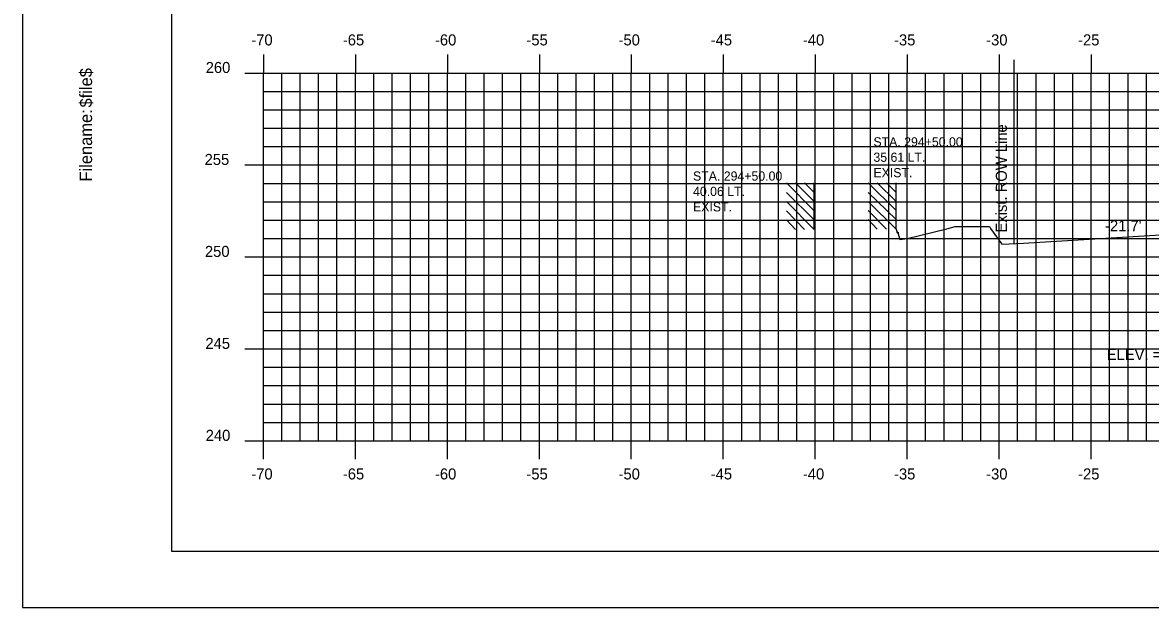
# Model space of a CAD drawing. Extents: x 859352 to 859522, y 366268 to 366378.
# Drawn here: x 859352 to 859413.3, y 366268.2 to 366300 of the extents above; entities that cross this region are included whole.
import ezdxf

# ---------------------------------------------------------------- set-up
doc = ezdxf.new("R2010")
doc.units = 0
for name, color, linetype in [('BORDER', 7, 'Continuous'), ('D_Text_Monospaced', 7, 'Continuous'), ('D_Text_Standard', 7, 'Continuous'), ('E_ROW_Line', 7, 'Continuous'), ('H_V ANNOTATION', 7, 'Continuous'), ('MAJOR', 7, 'Continuous'), ('MINOR', 7, 'Continuous'), ('PLOT BOUNDARY', 7, 'Continuous'), ('S_Buildings', 7, 'Continuous'), ('S_Roadway_Centerline', 7, 'Continuous')]:
    doc.layers.add(name, color=color, linetype=linetype)

msp = doc.modelspace()

# ---------------------------------------------------------------- linework, layer by layer
at = {"layer": 'BORDER'}
for p, q in [((859360.13, 366376.236), (859360.13, 366271.236)), ((859360.13, 366271.236), (859520.13, 366271.236))]:
    msp.add_line(p, q, dxfattribs=at)
at = {"layer": 'E_ROW_Line'}
msp.add_line((859405.943, 366287.961), (859405.943, 366297.961), dxfattribs=at)
at = {"layer": 'MAJOR'}
for p, q in [((859365.129, 366298.238), (859365.129, 366297.236)), ((859370.129, 366298.238), (859370.129, 366297.236)), ((859375.129, 366298.238), (859375.129, 366297.236)), ((859380.129, 366298.238), (859380.129, 366297.236)), ((859385.129, 366298.238), (859385.129, 366297.236)), ((859390.129, 366298.238), (859390.129, 366297.236)), ((859395.129, 366298.238), (859395.129, 366297.236)), ((859400.129, 366298.238), (859400.129, 366297.236)), ((859405.129, 366298.238), (859405.129, 366297.236)), ((859410.129, 366298.238), (859410.129, 366297.236)), ((859364.127, 366297.236), (859365.129, 366297.236)), ((859365.129, 366297.236), (859505.129, 366297.236)), ((859365.129, 366277.236), (859365.129, 366297.236)), ((859365.129, 366277.236), (859365.129, 366297.236)), ((859365.129, 366297.236), (859505.129, 366297.236)), ((859370.129, 366277.236), (859370.129, 366297.236)), ((859375.129, 366277.236), (859375.129, 366297.236)), ((859380.129, 366277.236), (859380.129, 366297.236)), ((859385.129, 366277.236), (859385.129, 366297.236)), ((859390.129, 366277.236), (859390.129, 366297.236)), ((859395.129, 366277.236), (859395.129, 366297.236)), ((859400.129, 366277.236), (859400.129, 366297.236)), ((859405.129, 366277.236), (859405.129, 366297.236)), ((859410.129, 366277.236), (859410.129, 366297.236)), ((859364.127, 366292.236), (859365.129, 366292.236)), ((859365.129, 366292.236), (859505.129, 366292.236)), ((859364.127, 366287.236), (859365.129, 366287.236)), ((859365.129, 366287.236), (859505.129, 366287.236)), ((859364.127, 366282.236), (859365.129, 366282.236)), ((859365.129, 366282.236), (859505.129, 366282.236)), ((859364.127, 366277.236), (859365.129, 366277.236)), ((859365.129, 366277.236), (859505.129, 366277.236)), ((859365.129, 366277.236), (859505.129, 366277.236)), ((859365.129, 366276.234), (859365.129, 366277.236)), ((859370.129, 366276.234), (859370.129, 366277.236)), ((859375.129, 366276.234), (859375.129, 366277.236)), ((859380.129, 366276.234), (859380.129, 366277.236)), ((859385.129, 366276.234), (859385.129, 366277.236)), ((859390.129, 366276.234), (859390.129, 366277.236)), ((859395.129, 366276.234), (859395.129, 366277.236)), ((859400.129, 366276.234), (859400.129, 366277.236)), ((859405.129, 366276.234), (859405.129, 366277.236)), ((859410.129, 366276.234), (859410.129, 366277.236))]:
    msp.add_line(p, q, dxfattribs=at)
at = {"layer": 'MINOR'}
for p, q in [((859366.129, 366277.236), (859366.129, 366297.236)), ((859367.129, 366277.236), (859367.129, 366297.236)), ((859368.129, 366277.236), (859368.129, 366297.236)), ((859369.129, 366277.236), (859369.129, 366297.236)), ((859371.129, 366277.236), (859371.129, 366297.236)), ((859372.129, 366277.236), (859372.129, 366297.236)), ((859373.129, 366277.236), (859373.129, 366297.236)), ((859374.129, 366277.236), (859374.129, 366297.236)), ((859376.129, 366277.236), (859376.129, 366297.236)), ((859377.129, 366277.236), (859377.129, 366297.236)), ((859378.129, 366277.236), (859378.129, 366297.236)), ((859379.129, 366277.236), (859379.129, 366297.236)), ((859381.129, 366277.236), (859381.129, 366297.236)), ((859382.129, 366277.236), (859382.129, 366297.236)), ((859383.129, 366277.236), (859383.129, 366297.236)), ((859384.129, 366277.236), (859384.129, 366297.236)), ((859386.129, 366277.236), (859386.129, 366297.236)), ((859387.129, 366277.236), (859387.129, 366297.236)), ((859388.129, 366277.236), (859388.129, 366297.236)), ((859389.129, 366277.236), (859389.129, 366297.236)), ((859391.129, 366277.236), (859391.129, 366297.236)), ((859392.129, 366277.236), (859392.129, 366297.236)), ((859393.129, 366277.236), (859393.129, 366297.236)), ((859394.129, 366277.236), (859394.129, 366297.236)), ((859396.129, 366277.236), (859396.129, 366297.236)), ((859397.129, 366277.236), (859397.129, 366297.236)), ((859398.129, 366277.236), (859398.129, 366297.236)), ((859399.129, 366277.236), (859399.129, 366297.236)), ((859401.129, 366277.236), (859401.129, 366297.236)), ((859402.129, 366277.236), (859402.129, 366297.236)), ((859403.129, 366277.236), (859403.129, 366297.236)), ((859404.129, 366277.236), (859404.129, 366297.236)), ((859406.129, 366277.236), (859406.129, 366297.236)), ((859407.129, 366277.236), (859407.129, 366297.236)), ((859408.129, 366277.236), (859408.129, 366297.236)), ((859409.129, 366277.236), (859409.129, 366297.236)), ((859411.129, 366277.236), (859411.129, 366297.236)), ((859412.129, 366277.236), (859412.129, 366297.236)), ((859413.129, 366277.236), (859413.129, 366297.236)), ((859365.129, 366296.236), (859505.129, 366296.236)), ((859365.129, 366296.236), (859366.131, 366296.236)), ((859365.129, 366295.236), (859505.129, 366295.236)), ((859365.129, 366295.236), (859366.131, 366295.236)), ((859365.129, 366294.236), (859505.129, 366294.236)), ((859365.129, 366294.236), (859366.131, 366294.236)), ((859365.129, 366293.236), (859505.129, 366293.236)), ((859365.129, 366293.236), (859366.131, 366293.236)), ((859365.129, 366291.236), (859505.129, 366291.236)), ((859365.129, 366291.236), (859366.131, 366291.236)), ((859365.129, 366290.236), (859505.129, 366290.236)), ((859365.129, 366290.236), (859366.131, 366290.236)), ((859365.129, 366289.236), (859505.129, 366289.236)), ((859365.129, 366289.236), (859366.131, 366289.236)), ((859365.129, 366288.236), (859505.129, 366288.236)), ((859365.129, 366288.236), (859366.131, 366288.236)), ((859365.129, 366286.236), (859505.129, 366286.236)), ((859365.129, 366286.236), (859366.131, 366286.236)), ((859365.129, 366285.236), (859505.129, 366285.236)), ((859365.129, 366285.236), (859366.131, 366285.236)), ((859365.129, 366284.236), (859505.129, 366284.236)), ((859365.129, 366284.236), (859366.131, 366284.236)), ((859365.129, 366283.236), (859505.129, 366283.236)), ((859365.129, 366283.236), (859366.131, 366283.236)), ((859365.129, 366281.236), (859505.129, 366281.236)), ((859365.129, 366281.236), (859366.131, 366281.236)), ((859365.129, 366280.236), (859505.129, 366280.236)), ((859365.129, 366280.236), (859366.131, 366280.236)), ((859365.129, 366279.236), (859505.129, 366279.236)), ((859365.129, 366279.236), (859366.131, 366279.236)), ((859365.129, 366278.236), (859505.129, 366278.236)), ((859365.129, 366278.236), (859366.131, 366278.236))]:
    msp.add_line(p, q, dxfattribs=at)
at = {"layer": 'PLOT BOUNDARY'}
msp.add_lwpolyline([(859352.036, 366268.177), (859522.036, 366268.177), (859522.036, 366378.177), (859352.036, 366378.177)], close=True, dxfattribs=at)
at = {"layer": 'S_Buildings'}
for p, q in [((859395.067, 366289.75), (859393.558, 366291.259)), ((859395.067, 366290.242), (859394.05, 366291.259)), ((859395.067, 366290.735), (859394.542, 366291.259)), ((859395.067, 366288.733), (859395.067, 366291.259)), ((859399.518, 366289.761), (859398.008, 366291.27)), ((859399.518, 366290.253), (859398.501, 366291.27)), ((859399.518, 366290.745), (859398.993, 366291.27)), ((859399.518, 366288.744), (859399.518, 366291.27)), ((859395.067, 366289.258), (859393.558, 366290.735)), ((859399.518, 366289.269), (859398.008, 366290.745)), ((859395.067, 366288.733), (859393.558, 366290.242)), ((859399.518, 366288.744), (859398.008, 366290.253)), ((859394.542, 366288.733), (859393.558, 366289.75)), ((859394.05, 366288.733), (859393.558, 366289.258)), ((859398.993, 366288.744), (859398.008, 366289.761)), ((859398.501, 366288.744), (859398.008, 366289.269))]:
    msp.add_line(p, q, dxfattribs=at)
at = {"layer": 'S_Roadway_Centerline'}
msp.add_lwpolyline([(859399.518, 366288.744), (859399.586, 366288.538), (859399.631, 366288.576), (859399.639, 366288.494), (859399.724, 366288.176), (859400.12, 366288.24), (859402.272, 366288.761), (859402.728, 366288.895), (859404.475, 366288.887), (859404.594, 366288.887), (859404.655, 366288.788), (859405.276, 366287.922), (859406.448, 366287.989), (859414.498, 366288.475)], dxfattribs=at)

# ---------------------------------------------------------------- texts
at = {"layer": 'BORDER'}
for s, p in [('$file$', (859355.815, 366295.362)), ('Filename:', (859355.815, 366291.335))]:
    msp.add_text(s, height=0.6696, rotation=90, dxfattribs=at).set_placement(p)
at = {"layer": 'D_Text_Monospaced'}
for s, height, p in [('STA. 294+50.00', 0.49998, (859398.29, 366293.242)), ('35.61 LT.', 0.5, (859398.29, 366292.408)), ('STA. 294+50.00', 0.49998, (859388.483, 366291.384)), ('EXIST. ', 0.5, (859398.29, 366291.568)), ('40.06 LT.', 0.5, (859388.483, 366290.55)), ('EXIST. ', 0.5, (859388.483, 366289.71))]:
    msp.add_text(s, height=height, dxfattribs=at).set_placement(p)
at = {"layer": 'D_Text_Standard'}
for s, p in [("-21.7'", (859410.88, 366288.626)), ('ELEV. = 244.70', (859410.969, 366281.636))]:
    msp.add_text(s, height=0.6, dxfattribs=at).set_placement(p)
at = {"layer": 'E_ROW_Line'}
msp.add_text('Exist. ROW Line', height=0.6, rotation=90, dxfattribs=at).set_placement((859405.543, 366288.561))
at = {"layer": 'H_V ANNOTATION'}
for s, p in [('-70', (859364.471, 366298.736)), ('-65', (859369.447, 366298.736)), ('-60', (859374.455, 366298.736)), ('-55', (859379.426, 366298.736)), ('-50', (859384.434, 366298.736)), ('-45', (859389.447, 366298.736)), ('-40', (859394.455, 366298.736)), ('-35', (859399.41, 366298.736)), ('-30', (859404.418, 366298.736)), ('-25', (859409.415, 366298.736)), ('260', (859361.992, 366297.236)), ('255', (859361.933, 366292.236)), ('250', (859361.949, 366287.236)), ('245', (859361.976, 366282.236)), ('240', (859361.992, 366277.236)), ('-70', (859364.471, 366275.136)), ('-65', (859369.447, 366275.136)), ('-60', (859374.455, 366275.136)), ('-55', (859379.426, 366275.136)), ('-50', (859384.434, 366275.136)), ('-45', (859389.447, 366275.136)), ('-40', (859394.455, 366275.136)), ('-35', (859399.41, 366275.136)), ('-30', (859404.418, 366275.136)), ('-25', (859409.415, 366275.136))]:
    msp.add_text(s, height=0.6, dxfattribs=at).set_placement(p)

doc.saveas('drawing.dxf')
